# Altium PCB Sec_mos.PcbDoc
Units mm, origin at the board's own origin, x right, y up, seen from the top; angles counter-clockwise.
Board outline 45.5 x 37.75 mm, 4 copper layers (Top Layer, Layer 1, Layer 2, Bottom Layer), stack 1.047 mm thick; 33 components, 16 nets, 98 pads, 225 vias.
Unrouted connection lines stored in the file: 1.
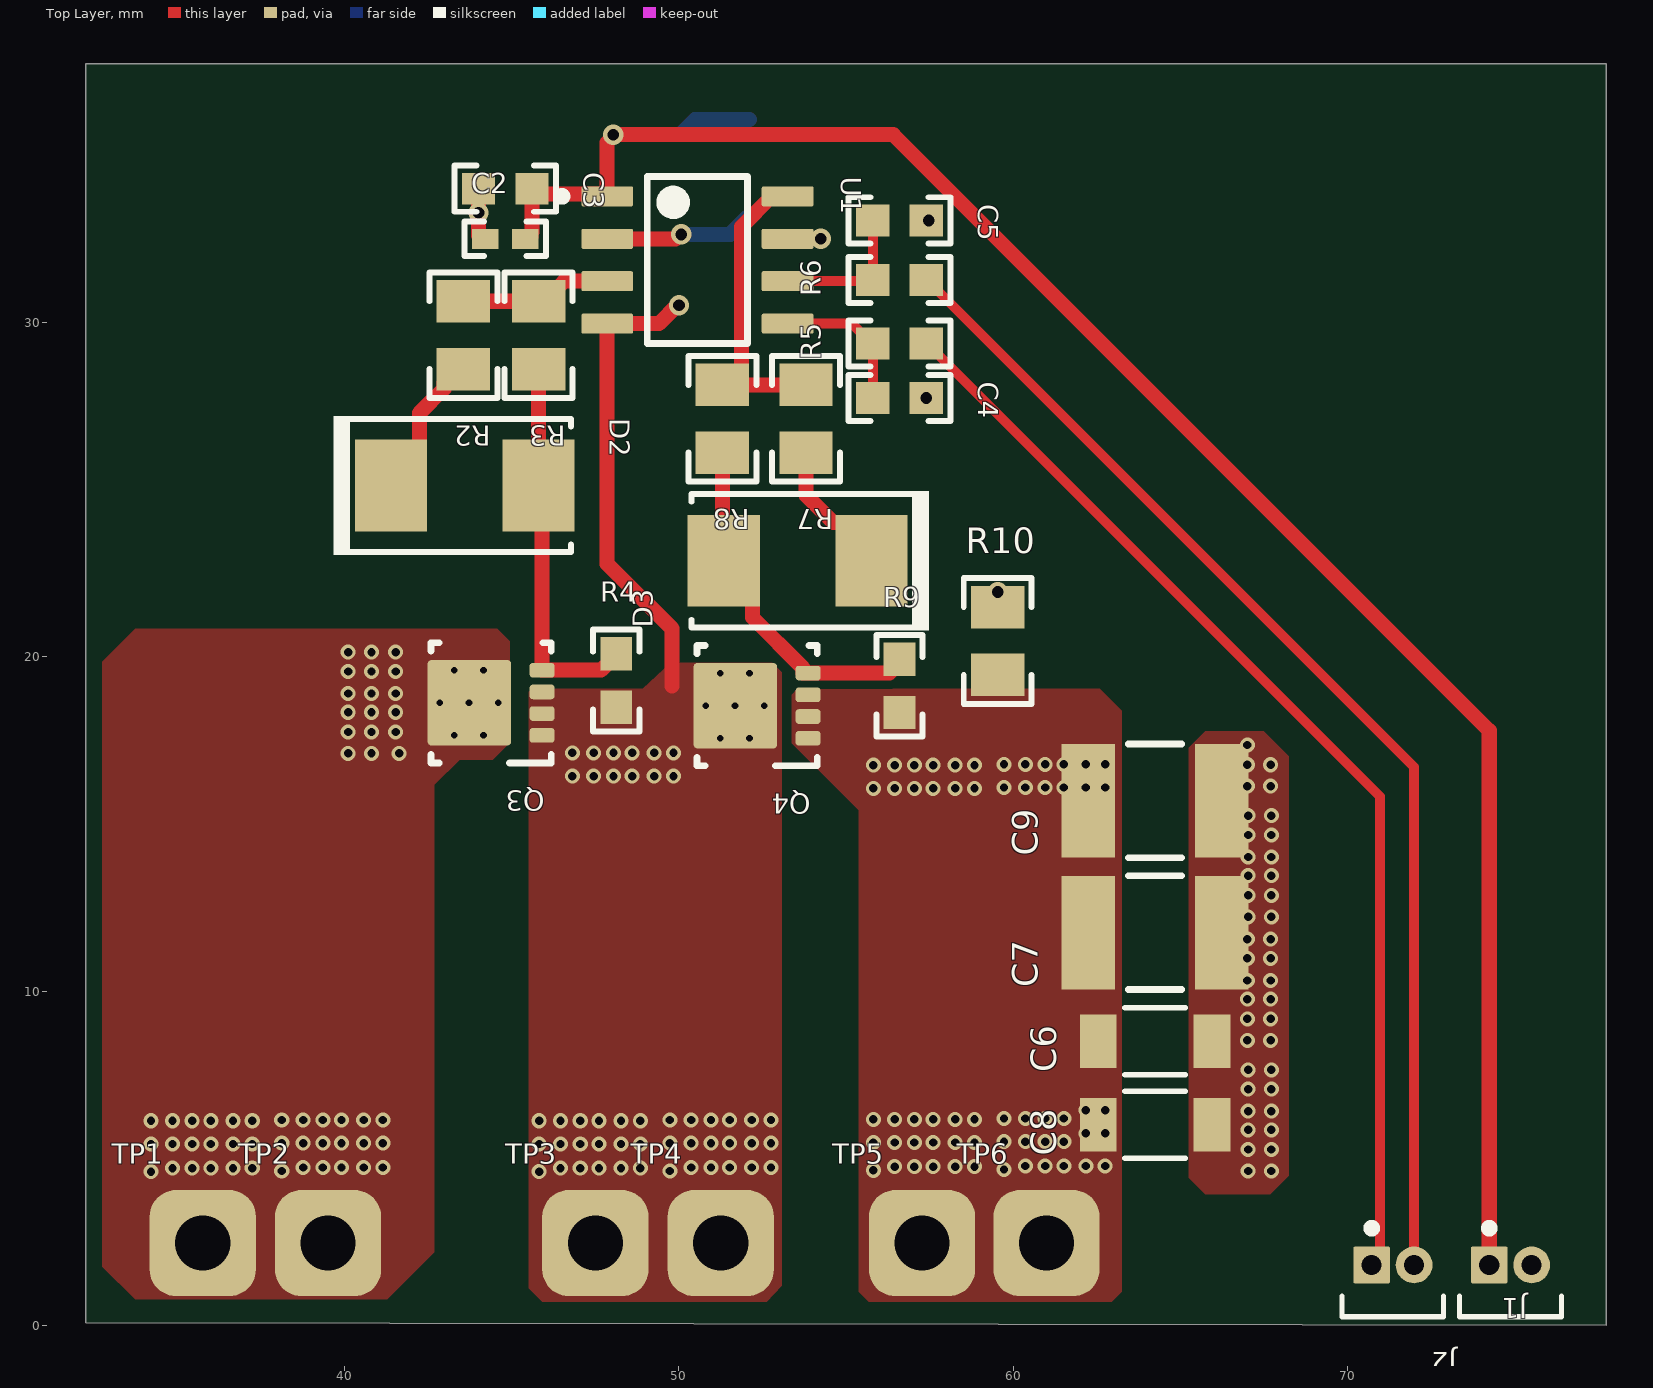
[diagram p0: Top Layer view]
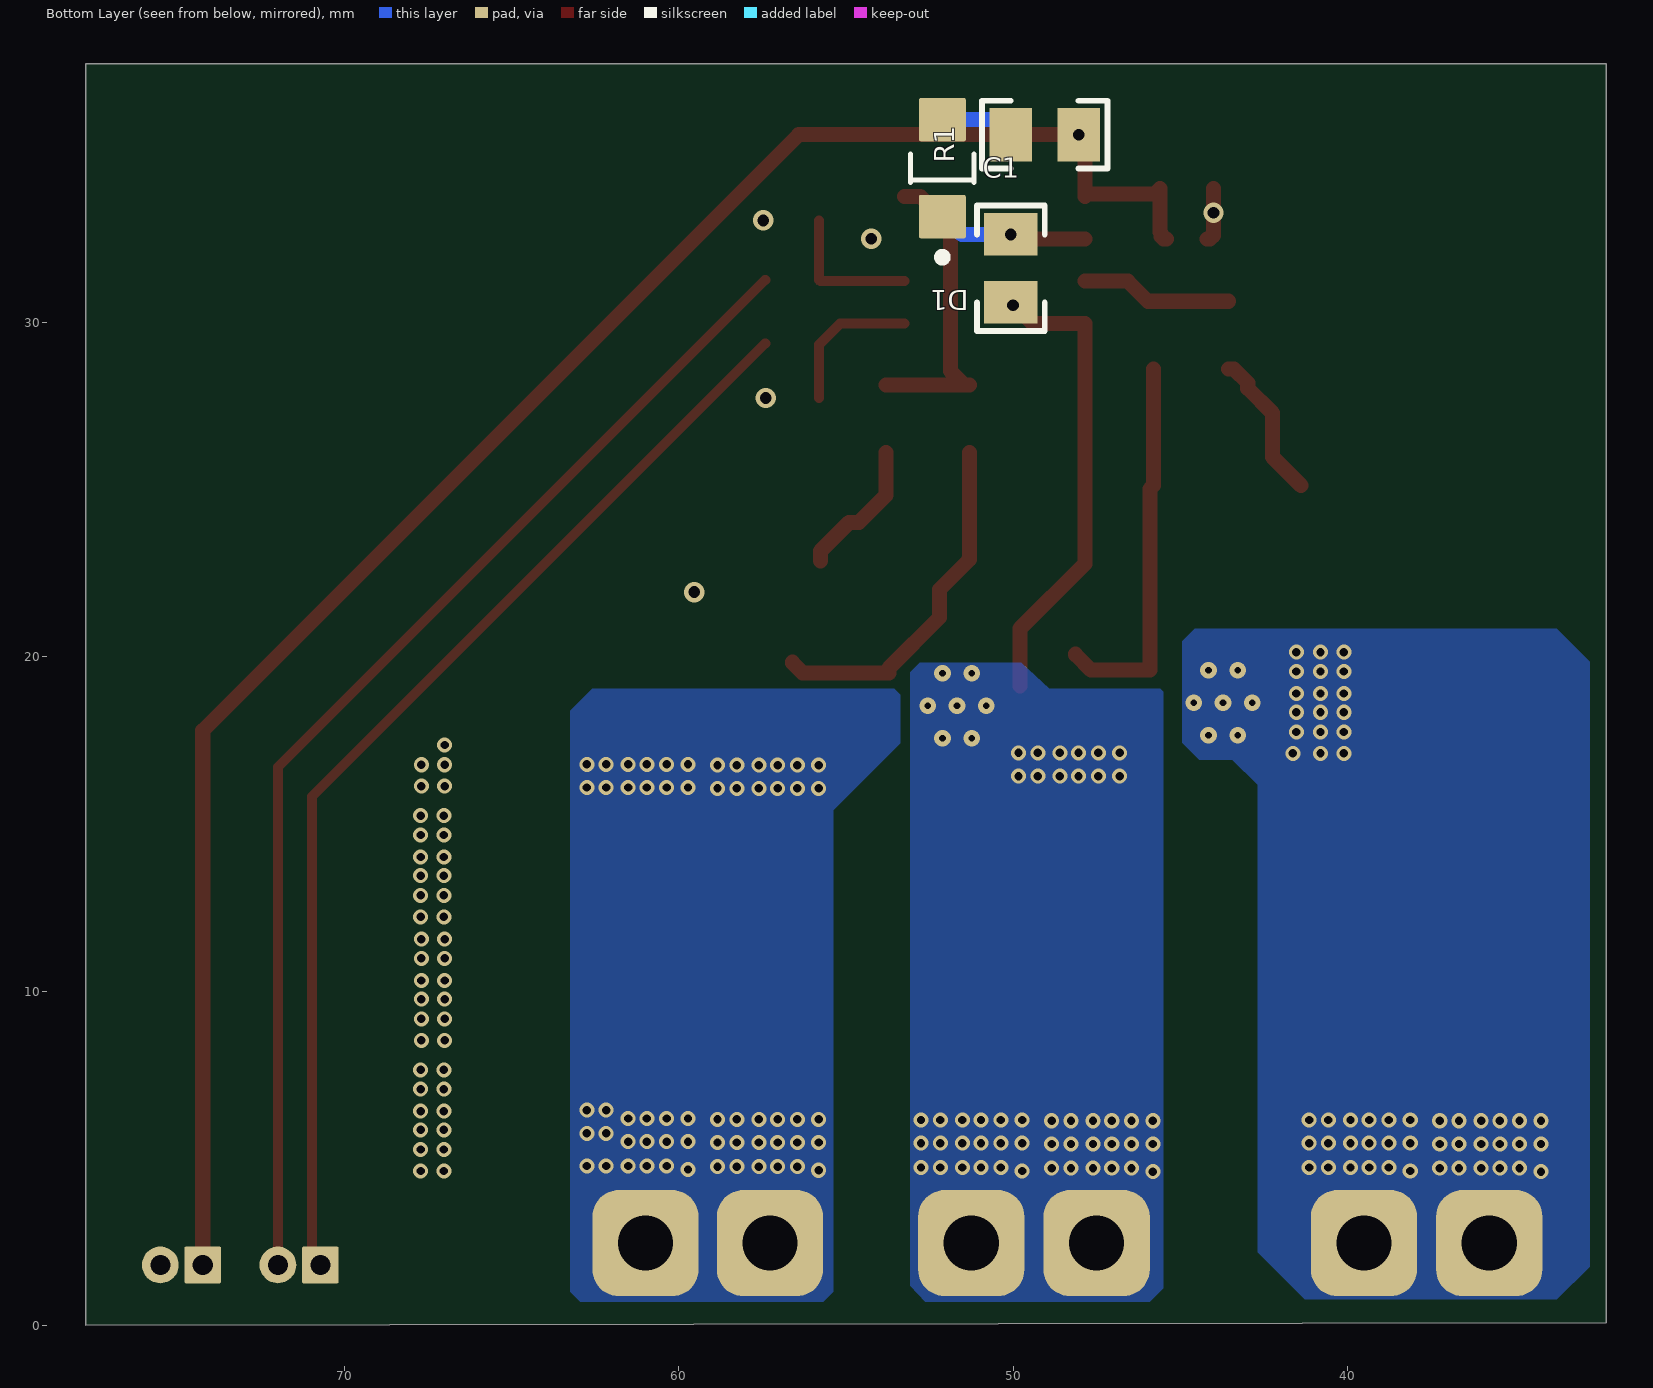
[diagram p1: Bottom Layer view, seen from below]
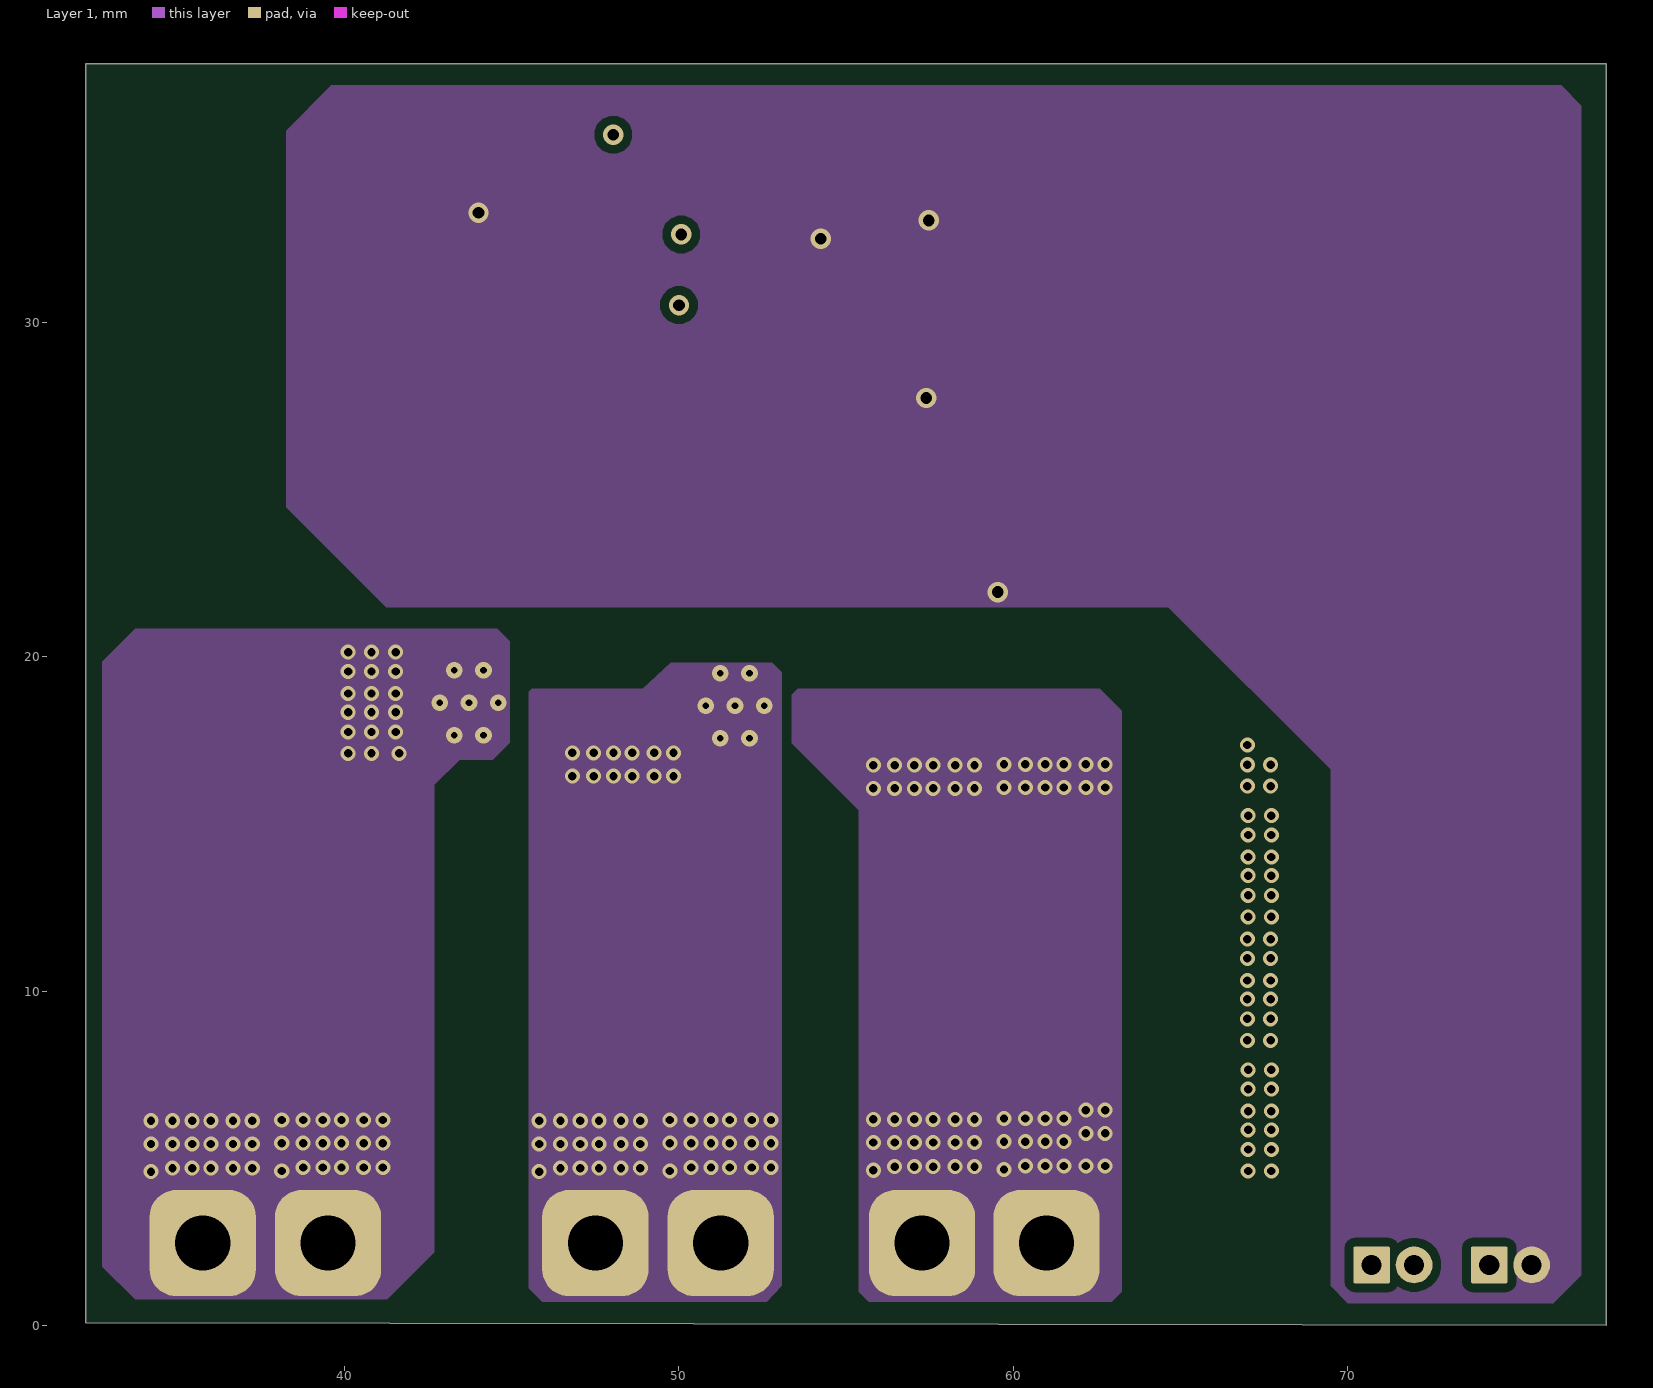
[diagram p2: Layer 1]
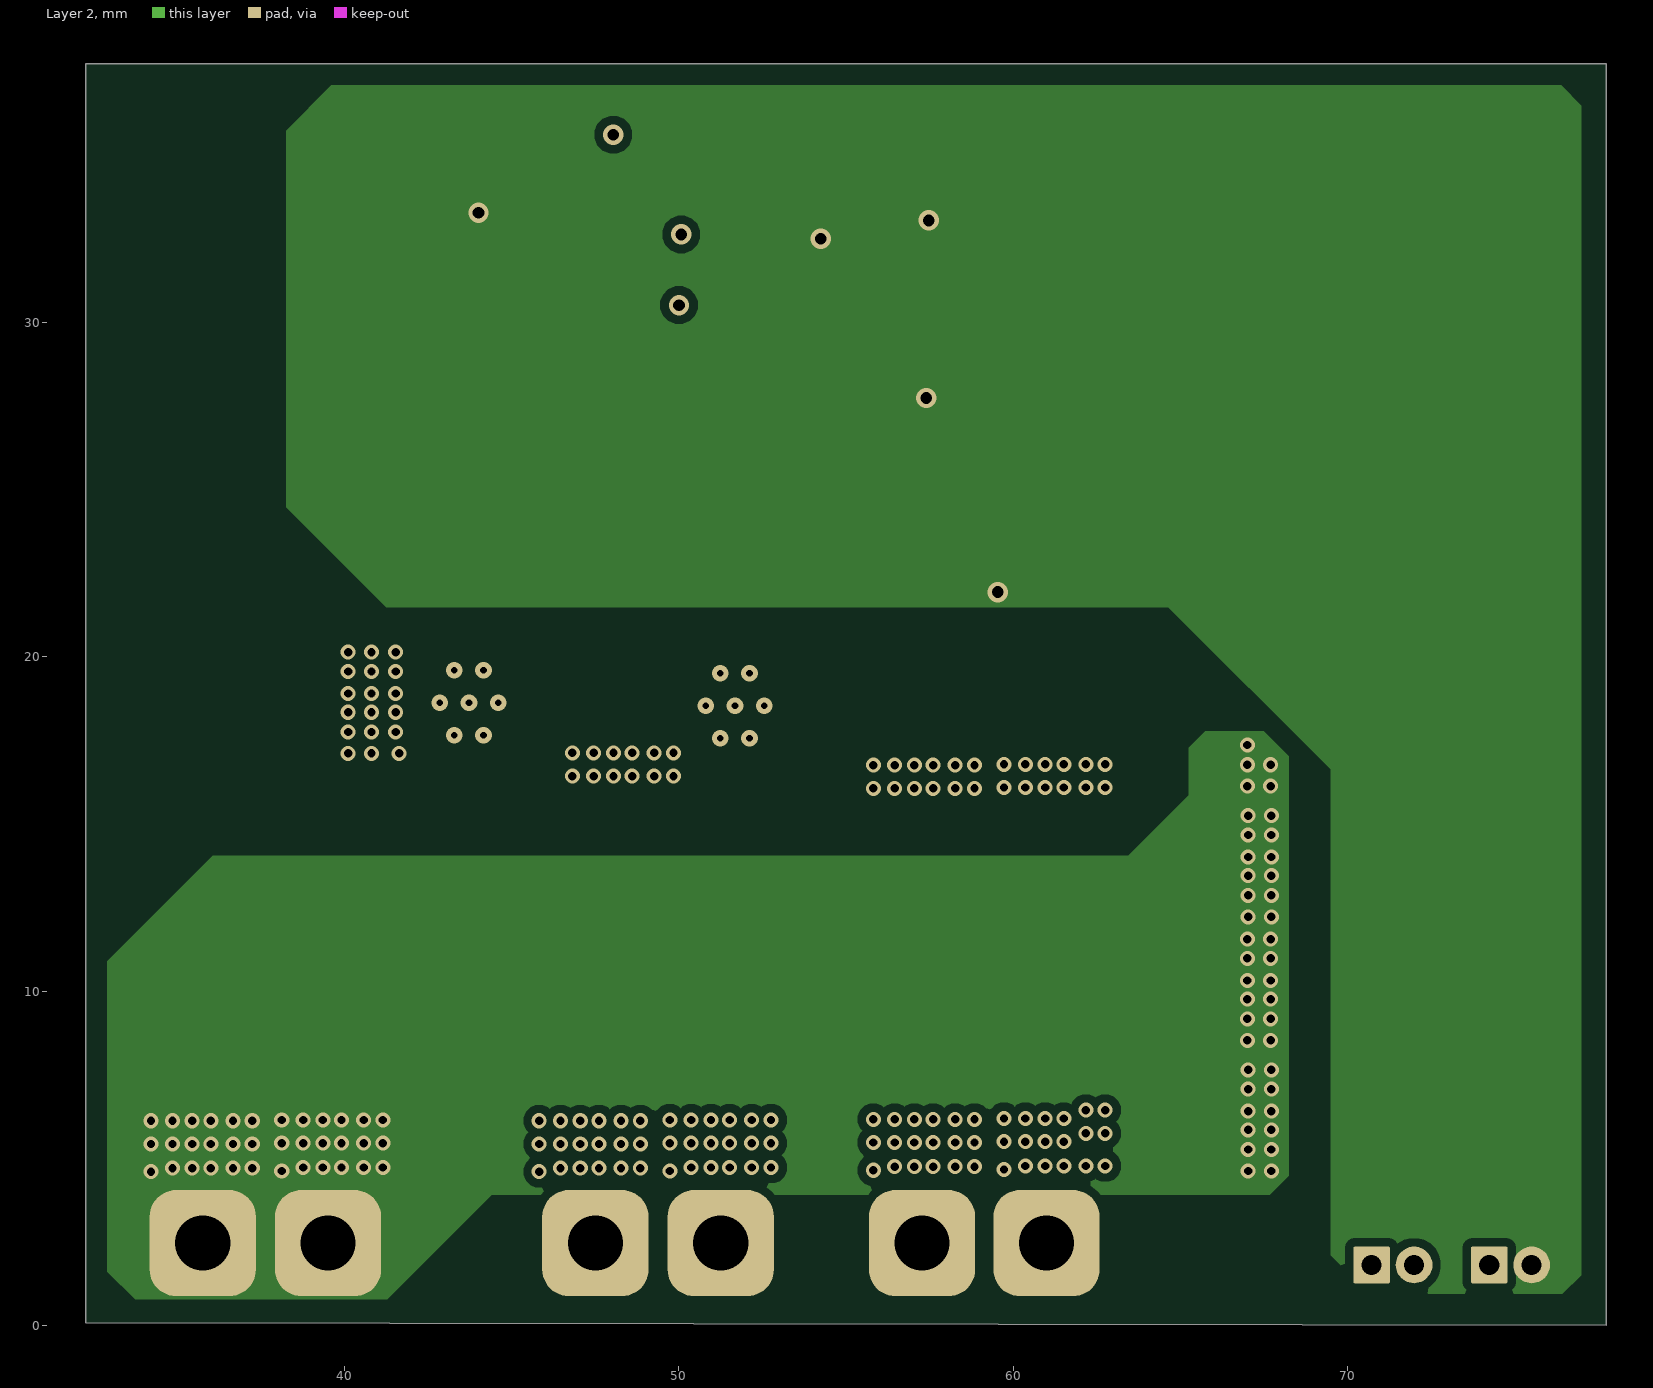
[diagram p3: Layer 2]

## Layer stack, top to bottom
Top Solder: solder mask 0.0102, Solder Resist, Dk 3.5
Top Layer: signal copper 0.07
Dielectric 1: prepreg 0.1168, PP-016, Dk 4.4
Layer 1: signal copper 0.07
Dielectric1: core 0.5334, Core-037, Dk 4.8
Layer 2: signal copper 0.07
Dielectric 2: prepreg 0.1168, PP-016, Dk 4.4
Bottom Layer: signal copper 0.07
Bottom Solder: solder mask 0.0102, Solder Resist, Dk 3.5

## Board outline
32.25,0.07 32.25,37.75 77.75,37.75 77.75,0

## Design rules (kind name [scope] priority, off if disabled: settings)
AcuteAngle [All] p1: minimum=4.50000000000000E+0001 checktracksonly=FALSE
AssemblyTestPointUsage [All] p1: valid=2
BoardOutlineClearance BoardOutlineClearance_MountingHoles [OnCopper and InComponentClass('Mounting Holes')] p1: gap=1 ignorepadtopadclearanceinfootprint=FALSE
BoardOutlineClearance BoardOutlineClearance_Poly [OnCopper and IsPoly] p2: gap=0.635 ignorepadtopadclearanceinfootprint=FALSE
BoardOutlineClearance [OnCopper and Not InComponentClass('Logo') and not InComponentClass('FiducialMark') and not InRegion(1000,500,4000,800) and not InPoly] p3: gap=1.016 ignorepadtopadclearanceinfootprint=FALSE
Clearance Clearance_Keepouts [((IsTrack Or IsArc) And Not InPoly) And IsFree and IsKeepOut vs ((IsTrack Or IsArc) And Not InPoly) And IsFree and IsKeepOut] p1: gap=0 ignorepadtopadclearanceinfootprint=FALSE
Clearance Clearance_Poly [InPolygon] p2: gap=0.254 ignorepadtopadclearanceinfootprint=TRUE
Clearance Clearance_FiducialMark [IsKeepOut and InComponentClass('FiducialMark') vs IsPad and InComponentClass('FiducialMark')] p3: gap=0 ignorepadtopadclearanceinfootprint=FALSE
Clearance [All] p4: gap=0.2 ignorepadtopadclearanceinfootprint=TRUE
ComponentClearance ComponentClearance_MountingHoles_FiducialMarks [InComponentClass('Mounting Holes') vs InComponentClass('FiducialMark')] p1: gap=1.27 collisioncheckmode=3 verticalgap=0.254 showdistances=FALSE
ComponentClearance ComponentClearance_Shunt [InComponentClass('Header') vs InComponentClass('Shunt')] p2: gap=0 collisioncheckmode=3 verticalgap=0 showdistances=FALSE
ComponentClearance ComponentClearance_Logo [InComponentClass('Logo')] p3: gap=0.762 collisioncheckmode=3 verticalgap=0.254 showdistances=FALSE
ComponentClearance ComponentClearance_ScrewToNut [(HasFootprint('NY PMS 440 0025 PH')) vs (HasFootprint('Keystone_1902C'))] p4: gap=0.127 collisioncheckmode=3 verticalgap=0.254 showdistances=FALSE
ComponentClearance ComponentClearance_MountingHoles [InComponentClass('Mounting Holes')] p5: gap=2.54 collisioncheckmode=3 verticalgap=2540 showdistances=FALSE
ComponentClearance ComponentClearance_SmallPassives [HasFootprint('0201*') or HasFootprint('0402*') or HasFootprint('0508') or HasFootprint('0603*') or HasFootprint('0612') or HasFootprint('0805*') or HasFootprint('0815*') or HasFootprint('0830*') or HasFootprint('1206*') or HasFootprint('1210*') or HasFootprint('1808*') or HasFootprint('1812*') or HasFootprint('1825*') or HasFootprint('2010*') or HasFootprint('2220*') or HasFootprint('2225*') or HasFootprint('2512*') or HasFootprint('2728*') or HasFootprint('3518*') vs HasFootprint('0201*') or HasFootprint('0402*') or HasFootprint('0508') or HasFootprint('0603*') or HasFootprint('0612') or HasFootprint('0805*') or HasFootprint('0815*') or HasFootprint('0830*') or HasFootprint('1206*') or HasFootprint('1210*') or HasFootprint('1808*') or HasFootprint('1812*') or HasFootprint('1825*') or HasFootprint('2010*') or HasFootprint('2220*') or HasFootprint('2225*') or HasFootprint('2512*') or HasFootprint('2728*') or HasFootprint('3518*')] p6: gap=0.38 collisioncheckmode=3 verticalgap=0.254 showdistances=FALSE
ComponentClearance ComponentClearance_THtoSMT [IsThruComponent vs IsSMTComponent] p7: gap=0.762 collisioncheckmode=3 verticalgap=0.762 showdistances=FALSE
ComponentClearance ComponentClearance_THtoTH [IsThruComponent vs IsThruComponent] p8: gap=0.508 collisioncheckmode=3 verticalgap=0.762 showdistances=FALSE
ComponentClearance [All] p9: gap=0.508 collisioncheckmode=3 verticalgap=0.254 showdistances=FALSE
DiffPairsRouting [All] p1: maxlimit=2.54 minlimit=0.254 mostfreqgap=0.254 toplayer_minwidth=0.381 toplayer_maxwidth=0.381 toplayer_prefwidth=0.381 midlayer1_minwidth=0.381 midlayer1_maxwidth=0.381 midlayer1_prefwidth=0.381 midlayer2_minwidth=0.381 midlayer2_maxwidth=0.381 midlayer2_prefwidth=0.381 bottomlayer_minwidth=0.381 bottomlayer_maxwidth=0.381 bottomlayer_prefwidth=0.381 maxuncoupledlength=25.4
FabricationTestPointUsage TestPointUsage [All] p1: valid=2 allowmultiple=FALSE
FabricationTestpoint Testpoint [All] p1: side=3 testpointundercomponent=TRUE minsize=1.016 maxsize=2.54 preferedsize=1.524 minholesize=0 maxholesize=1.016 preferedholesize=0.813 testpointgrid=0.025 allowsidetop=TRUE allowsidebottom=TRUE usegrid=TRUE gridtolerance=0
FanoutControl Fanout_LCC [IsLCC] p1: bgadir=Out bgaviamode=Centered fanoutstyle=Auto fanoutdirection=Alternating viagrid=0.025 // Fanout_LCC (Default Rule)
FanoutControl Fanout_BGA [IsBGA] p2: bgadir=Out bgaviamode=Centered fanoutstyle=Auto fanoutdirection=Alternating viagrid=0.025 // Fanout_BGA (Default Rule)
FanoutControl Fanout_Default [All] p4: bgadir=Out bgaviamode=Centered fanoutstyle=Auto fanoutdirection=Alternating viagrid=0.025 // Fanout_Default (Default Rule)
FanoutControl Fanout_Small [(CompPinCount < 5)] p5: bgadir=Out bgaviamode=Centered fanoutstyle=Auto fanoutdirection=OutThenIn viagrid=0.025 // Fanout_Small (Default Rule)
HoleSize [All] p1: absolutevalues=TRUE maxlimit=6.375 minlimit=0.2 maxpercent=80.000 minpercent=20.000
MinimumAnnularRing MinimumAnnularRing_ThermalPadVias [IsVia and InAnyComponent] p1: minimumring=0.15
MinimumAnnularRing [All] p2: minimumring=0.2
MinimumSolderMaskSliver MinimumSolderMaskSliver_Logo [InComponentClass('Logo') vs InComponentClass('Logo')] p1: minsoldermaskwidth=0.018
MinimumSolderMaskSliver [All] p2: minsoldermaskwidth=0.1
PlaneConnect [All] p1: planeconnectstyle=Relief reliefexpansion=0.254 reliefentries=4 reliefconductorwidth=0.254 reliefairgap=0.254
PolygonConnect [All] p1: connectstyle=Direct reliefconductorwidth=0.254 reliefentries=4 polygonreliefangle="90 Angle" airgapwidth=0.254
RoomDefinition Sec_mos [InComponentClass('Sec_mos')] p1: confinementstyle=ConfineIn formatcopy=TRUE lockcomponents=FALSE outline -17.577,-38.964 33.223,-38.964 33.223,-13.564 -17.577,-13.564
RoutingLayers [All] p1: top layer_v5=TRUE mid layer 1_v5=FALSE mid layer 2_v5=FALSE bottom layer_v5=TRUE
RoutingVias ThermalPadVias [IsVia and InAnyComponent] p1: holewidth=0.2 width=0.5 viastyle="Through Hole" minholewidth=0.2 minwidth=0.5 maxholewidth=0.33 maxwidth=0.6
RoutingVias [All] p2: holewidth=0.406 width=0.864 viastyle="Through Hole" minholewidth=0.2 minwidth=0.61 maxholewidth=1.016 maxwidth=1.651
SilkToBoardRegionClearance [Not ((IsComment or IsDesignator) And (Hide <> 'False')) and not InRegion(1000,500,4000,800)] p1:
SilkToSilkClearance SilkToSilkClearance_Pb-FreeLogo [(HasFootprint('Pb-Free_Overlay_Medium') OR HasFootprint('Pb-Free_Overlay_Small')) vs (HasFootprint('Pb-Free_Overlay_Medium') OR HasFootprint('Pb-Free_Overlay_Small'))] p1: silktosilkclearance=0
SilkToSilkClearance [All] p2: silktosilkclearance=0.1
SilkToSolderMaskClearance SilkToComponentPadClearance [(IsPad or IsFill or IsRegion) and InAnycomponent] p1: minsilkscreentomaskgap=0.127 clearancetoexposedcopper=TRUE
SilkToSolderMaskClearance "Silk to Solder Mask Opening" [All] p2: minsilkscreentomaskgap=0.1 clearancetoexposedcopper=FALSE
SolderMaskExpansion [All] p1: expansion=0.05 istentingtop=FALSE
UnRoutedNet [All] p1: checkbadconnections=TRUE
Width [All] p1: maxlimit=2.54 minlimit=0.152 preferedwidth=0.254 checkconnectedcopper=TRUE
13 further rules are at their usual default settings.

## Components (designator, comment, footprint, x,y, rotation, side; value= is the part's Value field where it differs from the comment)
C1 "08055C473JAT2A" 0805_HV 50.069,31.628 r90 bottom value=0.047uF
C2 "0402YC104KAT2A" 0402 44.803,32.513 r0 top value=0.1uF
C3 "GRM188Z71C475KE21D" 0603 44.803,34.013 r0 top value=4.7uF
C4 "06035A101FAT2A" 0603 56.603,27.748 r0 top value=100pF
C5 "06035A101FAT2A" 0603 56.603,33.063 r0 top value=100pF
C6 "C1206C223KDRACTU" 1206_190 64.25,8.5 r180 top value=0.022uF
C7 "C1812W104KDRACTU" 1812_254 64.25,11.75 r180 top value=0.1uF
C8 "C1206C223KDRACTU" 1206_190 64.25,6 r180 top value=0.022uF
C9 "C1812W104KDRACTU" 1812_254 64.25,15.694 r180 top value=0.1uF
D1 "V1FM10-M3/H" FP-V1FM10-M3-H_DO-219AB-MFG 52.115,34.628 r270 bottom
D2 "VS-20BQ030HM3/5BT" SMB 43.593,25.128 r0 top value=30V
D3 "VS-20BQ030HM3/5BT" SMB 53.553,22.878 r180 top value=30V
J1 "M50-3930242" FP-M50-3930242_HDR2-MFG 71.365,0.804 r0 top
J2 "M50-3930242" FP-M50-3930242_HDR2-MFG 74.885,0.804 r0 top
Q3 "CSD19537Q3" DQG0008A 44.38,18.628 r180 top value=100V
Q4 "CSD19537Q3" DQG0008A 52.341,18.54 r180 top value=100V
R1 "RC0805JR-072RL" 0805_HV 49.053,35.628 r0 bottom value=2.0
R2 "MCR10EZPJ000" 0805_HV 43.553,29.628 r270 top value=0
R3 "RC0805JR-071RL" 0805_HV 45.803,29.628 r270 top value=1.0
R4 "RT0603BRD07100KL" 0603 48.128,19.29 r90 top value=100k
R5 "TNPW060310R0BEEA" 0603 56.603,29.378 r180 top value=10.0
R6 "TNPW060310R0BEEA" 0603 56.603,31.278 r180 top value=10.0
R7 "MCR10EZPJ000" 0805_HV 53.803,27.128 r270 top value=0
R8 "RC0805JR-071RL" 0805_HV 51.303,27.128 r270 top value=1.0
R9 "RT0603BRD07100KL" 0603 56.603,19.136 r90 top value=100k
R10 "PMR10EZPJ000" 0805_HV 59.539,20.476 r90 top value=0
TP1 "3621-0-32-15-00-00-08-0" Mill-Max_3621-0-32-xx-00-00-08-0 35.75,0.07 r0 top
TP2 "3621-0-32-15-00-00-08-0" Mill-Max_3621-0-32-xx-00-00-08-0 39.5,0.07 r0 top
TP3 "3621-0-32-15-00-00-08-0" Mill-Max_3621-0-32-xx-00-00-08-0 47.5,0.07 r0 top
TP4 "3621-0-32-15-00-00-08-0" Mill-Max_3621-0-32-xx-00-00-08-0 51.25,0.07 r0 top
TP5 "3621-0-32-15-00-00-08-0" Mill-Max_3621-0-32-xx-00-00-08-0 57.275,0.07 r0 top
TP6 "3621-0-32-15-00-00-08-0" Mill-Max_3621-0-32-xx-00-00-08-0 61,0.07 r0 top
U1 "UCC27288D" D0008A-MFG 50.553,31.878 r0 top

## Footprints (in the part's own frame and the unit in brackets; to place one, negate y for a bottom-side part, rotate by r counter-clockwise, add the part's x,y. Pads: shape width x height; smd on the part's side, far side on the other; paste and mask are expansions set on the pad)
0402 [mm] "0402 from SM-752 data"
  rect 0.8x0.6 smd: 1(-0.6,0) 2(0.6,0)
  silkscreen extent -1.22,-0.52 1.22,0.52, body extent -0.55,-0.3 0.55,0.3, height 0.6
0603 [mm] "0603 from SM-752 data"
  rect 1x0.95 smd: 1(-0.8,0) 2(0.8,0)
  silkscreen extent -1.52,-0.69 1.52,0.69, body extent -0.87,-0.47 0.87,0.47, height 1
0805_HV [mil] "0805 with 30mil clearance between pads"
  rect 50x63 smd: 1(-40,0) 2(40,0)
  silkscreen extent -74,-40 74,40, body extent -43,-29 43,29, height 57
1206_190 [mm] "1206_190"
  rect 1.1x1.6 smd: 1(-1.7,0) 2(1.7,0)
  silkscreen extent -0.9,-1 0.9,1, body extent -1.75,-0.95 1.75,0.95, height 1.9
1812_254 [mm] "SMD, 2-Leads, Body 4.8x3.4mm"
  rect 1.6x3.4 smd: 1(-2,0) 2(2,0)
  silkscreen extent -0.8,-1.7 0.8,1.7, body extent -2.4,-1.7 2.4,1.7, height 2.54
D0008A-MFG [mm]
  rrect17% 1.55x0.6 smd paste+0 mask+0: 1(-2.7,1.905) 2(-2.7,0.635) 3(-2.7,-0.635) 4(-2.7,-1.905) 5(2.7,-1.905) 6(2.7,-0.635) 7(2.7,0.635) 8(2.7,1.905)
  silkscreen extent -4.17,-2.5 1.5,2.5, body extent -3.57,-2.75 3.57,2.75, height 0.25
DQG0008A [mm] "SMD, 8-Leads, Body 3.3x3.3mm, Pitch 0.65mm"
  rrect45% 0.75x0.44 smd paste-0.05 mask-0.05: 1(-1.525,0.975) 2(-1.525,0.325) 3(-1.525,-0.325) 4(-1.525,-0.975) 5(1.525,-0.975) 6(1.525,-0.325) 7(1.525,0.325) 8(1.525,0.975)
  rrect15% 0.676x1.125 on Top Paste: 9(-0.212,0.662) 9(-0.212,-0.663) 9(0.664,0.662) 9(0.664,-0.663)
  rrect6% 1.775x2.45 on Top Solder: 9(0.327,0)
  rrect8% 2.5x2.55 smd paste-1.5 mask-1.5: 9(0.65,0)
  rrect29% 0.5x0.34 on Top Solder: 9(1.175,0.975) 9(1.175,-0.325) 9(1.175,0.325) 9(1.175,-0.975)
  silkscreen extent -1.8,-1.8 1.8,1.8, body extent -1.65,-1.65 1.65,1.65, height 1.1
FP-M50-3930242_HDR2-MFG [mm]
  rrect9% 1.1x1.1 hole 0.6 paste-1000 mask+0: 1(-0.635,1)
  round 1.1 hole 0.6 paste-1000 mask+0: 2(0.635,1)
  silkscreen extent -1.52,-0.55 1.52,2.22, body extent -1.62,-4.85 1.62,1.65, height 0.25
FP-V1FM10-M3-H_DO-219AB-MFG [mm]
  rrect8% 1.3x1.4 smd paste+0 mask+0: 1(1.45,0) 2(-1.45,0)
  silkscreen extent -0.43,-0.95 2.79,0.95, body extent -1.85,-0.9 1.85,0.9, height 1.08
Mill-Max_3621-0-32-xx-00-00-08-0 [mm] "PCB Pin, 0.04\" DIA, R/A, Edge-Mount"
  rrect50% 3.18x3.18 hole 1.65: 1(0,2.388)
  body extent -1.59,-5.06 1.59,3.98, height 1.57
SMB [mm] "Molded Diode, 2-Leads, Body 5.4x3.6mm, IPC Medium Density, based on OnSemi component dimensions"
  rect 2.159x2.743 smd: 1(-2.21,0) 2(2.21,0)
  silkscreen extent -3.94,-2.08 3.17,2.08, body extent -2.7,-1.8 2.7,1.8, height 2.32

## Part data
C1: library part CMP-0007658-2, "CAP, CERM, 0.047 uF, 50 V, +/- 5%, X7R, 0805", Cap_Case=0805, Manufacturer=AVX, Supplier Part Number 1=478-3771-1-ND, TempCo=X7R, Tolerance_%=5%, Value1="0.035 ohm", Value2=50V, ValueDisplayed=0.047uF
C2: library part CMP-0006201-2, "CAP, CERM, 0.1 uF, 16 V, +/- 10%, X7R, 0402", Cap_Case=0402, Manufacturer=AVX, Supplier Part Number 1=478-7888-1-ND, TempCo=X7R, Tolerance_%=10%, Value1=Unknown, Value2=16V, ValueDisplayed=0.1uF
C3: library part CMP-0064936-4, "CAP, CERM, 4.7 uF, 16 V,+/- 10%, X7R, 0603", Cap_Case=0603, Manufacturer=MuRata, TempCo=X7R, Tolerance_%=10%, Value1=Unknown, Value2=16V, ValueDisplayed=4.7uF
C4 C5: library part CMP-0006762-4, "CAP, CERM, 100 pF, 50 V, +/- 1%, C0G/NP0, 0603", Cap_Case=0603, Manufacturer=AVX, Supplier Part Number 1=478-6202-1-ND, TempCo=C0G/NP0, Tolerance_%=1%, Value1=Unknown, Value2=50V, ValueDisplayed=100pF
C6 C8: library part CMP-0084048-1, "CAP, CERM, 0.022 µF, 1000 V,+/- 10%, X7R, AEC-Q200 Grade 1, 1206", Cap_Case=1206, Manufacturer=Kemet, TempCo=X7R, Tolerance_%=10%, Value2=1000V, ValueDisplayed=0.022µF
C7 C9: library part CMP-0009326-2, "CAP, CERM, 0.1 uF, 1000 V, +/- 10%, X7R, 1812", Cap_Case=1812, Manufacturer=Kemet, Supplier Part Number 1=399-6523-1-ND, TempCo=X7R, Tolerance_%=10%, Value1=Unknown, Value2=1000V, ValueDisplayed=0.1uF
D1: library part CMP-0093639-2, "Diode Schottky 1A Surface Mount DO-219AB (SMF)", Digikey Part Number=112-V1FM10-M3/HCT-ND, Forward Current=1A, Manufacturer=Vishay, Max Surge Forward Current=30A, Mouser Part Number=78-V1FM10-M3/H, Operating Temperature Range="-40°C to +175°C", Peak Reverse Current=0.2uA, ValueDisplayed=95pF
D2 D3: library part CMP-0028909-2, "Diode, Schottky, 30 V, 2 A, AEC-Q101, SMB", Manufacturer=Vishay-Semiconductor, Value1=2A, Value2=0.47V
J1 J2: library part CMP-0097272-1, "Conn Unshrouded HDR 2 POS 1.27mm Solder RA Through Hole Box", Current_A=1A, Digikey Part Number=952-3614-ND, Manufacturer=Harwin, Mouser Part Number=855-M50-3930242, Operating Temperature Range="-40°C to +105°C"
Q3 Q4: library part CMP-0000967-2, "MOSFET, N-CH, 100 V, 50 A, DQG0008A (VSON-CLIP-8)", Alternate Manufacturer=None, Manufacturer="Texas Instruments", Supplier Part Number 1=CSD19537Q3-ND, Value2="16 nC"
R1: library part CMP-0020815-2, "RES, 2.0, 5%, 0.125 W, 0805", Manufacturer="Yageo America", Power_W=125mW, Supplier Part Number 1=311-2.0ARCT-ND, TempCo="200 ppm/C", Tolerance_%=5%, Value2=0.125W, Value_Code=2R00, ValueDisplayed=2.0
R2 R7: library part CMP-0020802-2, "RES, 0, 5%, 0.125 W, 0805", Manufacturer=Rohm, Power_W=125mW, Supplier Part Number 1=RHM0.0ARCT-ND, TempCo="400 ppm/C", Tolerance_%=5%, Value2=0.125W, Value_Code=0000, ValueDisplayed=0
R3 R8: library part CMP-0020811-2, "RES, 1.0, 5%, 0.125 W, 0805", Manufacturer="Yageo America", Power_W=125mW, Supplier Part Number 1=311-1.0ARCT-ND, TempCo="200 ppm/C", Tolerance_%=5%, Value2=0.125W, Value_Code=1R00, ValueDisplayed=1.0
R4 R9: library part CMP-0023630-3, "RES, 100 k, 0.1%, 0.1 W, 0603", Manufacturer="Yageo America", Power_W=100mW, Supplier Part Number 1=603-RT0603BRD07100KL, TempCo="25 ppm/C", Tolerance_%=0.1%, Value2=0.1W, Value_Code=100k
R5 R6: library part CMP-0025687-2, "RES, 10.0, 0.1%, 0.1 W, 0603", Manufacturer=Vishay-Dale, Power_W=100mW, Supplier Part Number 1=TNP10.0AACT-ND, TempCo="25 ppm/C", Tolerance_%=0.1%, Value2=0.1W, Value_Code=10R0, ValueDisplayed=10.0
R10: library part CMP-0081857-1, "RES, 0, 0%,  W, AEC-Q200 Grade 0, 0805", Manufacturer=Rohm, Supplier Part Number 1=755-PMR10EZPJ000, Tolerance_%=0%, Value2=W, Value_Code=0
TP1 TP2 TP3 TP4 TP5 TP6: library part CMP-0082316-1, "PCB Pin, 0.04\" DIA, Edge-Mount", Manufacturer=Mill-Max, Supplier Part Number 1=575-3621032150000
U1: library part CMP-0088395-1, "120-V Boot, 3-A Peak, High-Frequency High-Side/Low-Side Driver", Manufacturer="Texas Instruments", Max Supply Voltage=16V, Min Supply Voltage=8V, Nominal Supply Current=2.2uA, Operating Temperature Range="-40°C to +140°C"

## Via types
v1: diameter 0.45, hole 0.25, Top Layer to Bottom Layer, tented both sides, 203 vias
v2: diameter 0.5, hole 0.2, Top Layer to Bottom Layer, 12 vias
v3: diameter 0.61, hole 0.35, Top Layer to Bottom Layer, tented both sides, 8 vias
v4: diameter 0.5, hole 0.2, Top Layer to Bottom Layer, tented both sides, 2 vias

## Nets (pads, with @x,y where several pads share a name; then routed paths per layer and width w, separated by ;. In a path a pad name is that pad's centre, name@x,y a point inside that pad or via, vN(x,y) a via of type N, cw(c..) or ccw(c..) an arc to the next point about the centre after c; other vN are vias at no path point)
+12V: C2.2 C3.2 J2.1 R1.1 U1.1 | length 55
  Top Layer w0.45: C2.2 45.503,32.513 45.578,32.588 45.578,32.688 45.603,32.713 C3.2 45.758,33.858 47.778,33.858 U1.1 v3@47.853,35.401 ; v3(48.037,35.628) 56.414,35.628 74.25,17.792 J2.1@74.25,2.045
GND_sec: C2.1 C3.1 C4.2 C5.2 C6.2 C7.2 C8.2 C9.2 J2.2 Q4.1 Q4.2 Q4.3 R9.1 R10.1 R10.2 TP5.1 TP6.1 U1.7 | length 1.6
  Top Layer w0.45: C3.1 44.003,32.613 44.103,32.513 C2.1
  other v1: 55.817,4.639 59.728,4.662 56.457,4.744 57.048,4.744 57.607,4.744 58.267,4.744 58.845,4.744 60.368,4.767 60.958,4.767 61.517,4.767 62.178,4.767 62.755,4.767 55.817,5.469 56.457,5.469 57.048,5.469 57.607,5.469 58.267,5.469 58.845,5.469 59.728,5.492 60.368,5.492 60.958,5.492 61.517,5.492 62.178,5.742 62.755,5.742 55.817,6.164 56.457,6.164 57.048,6.164 57.607,6.164 58.267,6.164 58.845,6.164 59.728,6.187 60.368,6.187 60.958,6.187 61.517,6.187 62.178,6.437 62.755,6.437 55.817,16.068 56.457,16.068 57.048,16.068 57.607,16.068 58.267,16.068 58.845,16.068 59.728,16.091 60.368,16.091 60.958,16.091 61.517,16.091 62.178,16.091 62.755,16.091 55.817,16.763 56.457,16.763 57.048,16.763 57.607,16.763 58.267,16.763 58.845,16.763 59.728,16.786 60.368,16.786 60.958,16.786 61.517,16.786 62.178,16.786 62.755,16.786
  other v3: 59.539,21.94 57.403,27.748 54.249,32.513 57.478,33.063 44.003,33.288
NetC1_1: C1.1 Q3.1 Q3.2 Q3.3 Q4.5 Q4.6 Q4.7 Q4.8 Q4.9@51.691,18.54 R4.1 TP3.1 TP4.1 U1.4 | length 14
  Top Layer w0.45: 49.789,19.136 49.789,20.847 47.853,22.784 U1.4 49.405,29.973 49.96,30.528 v3(50.003,30.528)
  other v1: 45.817,4.594 49.728,4.617 46.457,4.699 47.048,4.699 47.607,4.699 48.267,4.699 48.845,4.699 50.368,4.722 50.958,4.722 51.517,4.722 52.178,4.722 52.755,4.722 45.817,5.424 46.457,5.424 47.048,5.424 47.607,5.424 48.267,5.424 48.845,5.424 49.728,5.447 50.368,5.447 50.958,5.447 51.517,5.447 52.178,5.447 52.755,5.447 45.817,6.119 46.457,6.119 47.048,6.119 47.607,6.119 48.267,6.119 48.845,6.119 49.728,6.142 50.368,6.142 50.958,6.142 51.517,6.142 52.178,6.142 52.755,6.142 46.81,16.432 47.45,16.432 48.041,16.432 48.6,16.432 49.26,16.432 49.838,16.432 46.81,17.127 47.45,17.127 48.041,17.127 48.6,17.127 49.26,17.127 49.838,17.127
  other v2: 51.239,17.565 52.115,17.565 51.677,18.54 52.553,18.54 51.239,19.515 52.115,19.515
  other v4: 50.801,18.54
NetC1_2: C1.2 D1.1 U1.2 | length 4.5
  Top Layer w0.45: U1.2 49.895,32.513 50.026,32.644 v3(50.069,32.644)
  Bottom Layer w0.45: v3(50.069,32.644) 51.531,32.644 52.065,33.178 D1.1
NetC4_1: C4.1 R5.2 U1.5 | length 4.4
  Top Layer w0.3: U1.5 55.183,29.973 55.803,29.353 C4.1
NetC5_1: C5.1 R6.2 U1.6 | length 4.3
  Top Layer w0.3: U1.6 55.767,31.243 R6.2 C5.1
NetC6_1: C6.1 C7.1 C8.1 C9.1 Q3.5 Q3.6 Q3.7 Q3.8 Q3.9@43.73,18.628 TP1.1 TP2.1
  other v1: 34.204,4.594 38.114,4.617 67.035,4.617 67.73,4.617 34.844,4.699 35.434,4.699 35.993,4.699 36.654,4.699 37.231,4.699 38.754,4.722 39.345,4.722 39.904,4.722 40.564,4.722 41.142,4.722 67.035,5.257 67.73,5.257 34.204,5.424 34.844,5.424 35.434,5.424 35.993,5.424 36.654,5.424 37.231,5.424 38.114,5.447 38.754,5.447 39.345,5.447 39.904,5.447 40.564,5.447 41.142,5.447 67.035,5.848 67.73,5.848 34.204,6.119 34.844,6.119 35.434,6.119 35.993,6.119 36.654,6.119 37.231,6.119 38.114,6.142 38.754,6.142 39.345,6.142 39.904,6.142 40.564,6.142 41.142,6.142 67.035,6.407 67.73,6.407 67.035,7.067 67.73,7.067 67.035,7.645 67.73,7.645 67.012,8.528 67.707,8.528 67.012,9.168 67.707,9.168 67.012,9.758 67.707,9.758 67.012,10.317 67.707,10.317 67.012,10.978 67.707,10.978 67.012,11.555 67.707,11.555 67.035,12.223 67.73,12.223 67.035,12.863 67.73,12.863 67.035,13.453 67.73,13.453 67.035,14.012 67.73,14.012 67.035,14.673 67.73,14.673 67.035,15.25 67.73,15.25 67.012,16.133 67.707,16.133 67.012,16.773 67.707,16.773 40.104,17.114 40.799,17.114 41.629,17.114 67.012,17.364 40.104,17.754 40.799,17.754 41.524,17.754 40.104,18.345 40.799,18.345 41.524,18.345 40.104,18.904 40.799,18.904 41.524,18.904 40.104,19.564 40.799,19.564 41.524,19.564 40.104,20.142 40.799,20.142 41.524,20.142
  other v2: 43.278,17.653 44.154,17.653 43.716,18.628 44.592,18.628 43.278,19.603 44.154,19.603
  other v4: 42.84,18.628
NetD1_2: D1.2 R1.2 | length 2.3
  Bottom Layer w0.45: R1.2 50.069,35.668 50.479,36.078 D1.2
NetD2_1: D2.1 R2.2 | length 4.5
  Top Layer w0.45: D2.1 42.237,25.982 42.237,27.296 42.978,28.037 42.978,28.202 43.388,28.612 R2.2
NetD2_2: D2.2 Q3.4 R3.2 R4.2 | length 11.5
  Top Layer w0.45: R3.2 D2.2 45.905,25.025 Q3.4 47.665,19.603 48.128,20.065 R4.2
NetD3_1: D3.1 R7.2 | length 4.2
  Top Layer w0.45: R7.2 53.803,24.838 54.616,24.024 54.908,24.024 55.763,23.17 D3.1
NetD3_2: D3.2 Q4.4 R8.2 R9.2 | length 10.6
  Top Layer w0.45: R8.2 51.303,22.918 D3.2 52.197,22.023 52.197,21.184 53.716,19.665 53.716,19.52 53.721,19.515 Q4.4 56.295,19.515 56.603,19.823 R9.2@56.603,19.848
NetJ1_1: J1.1 R5.1 | length 33
  Top Layer w0.3: R5.1 57.428,29.378 70.98,15.826 J1.1@70.98,2
NetJ1_2: J1.2 R6.1 | length 35.5
  Top Layer w0.3: R6.1 57.428,31.278 72,16.706 J1.2
NetR2_1: R2.1 R3.1 U1.3 | length 4.5
  Top Layer w0.45: R2.1 R3.1 45.968,30.644 46.567,31.243 U1.3
NetR7_1: R7.1 R8.1 U1.8 | length 9.2
  Top Layer w0.45: R8.1 R8.1@51.468,28.144 ; U1.8 52.778,33.783 51.878,32.883 51.878,28.554 R8.1@51.468,28.144 ; R7.1 R8.1@51.468,28.144
pads on no net: Q3.9@43.205,17.653 Q3.9@43.205,18.303 Q3.9@43.205,18.953 Q3.9@43.205,19.603 Q3.9@43.716,17.965 Q3.9@43.716,19.29 Q3.9@44.053,18.628 Q3.9@44.592,17.965 Q3.9@44.592,19.29 Q4.9@51.166,17.565 Q4.9@51.166,18.215 Q4.9@51.166,18.865 Q4.9@51.166,19.515 Q4.9@51.677,17.878 Q4.9@51.677,19.203 Q4.9@52.013,18.54 Q4.9@52.553,17.878 Q4.9@52.553,19.203

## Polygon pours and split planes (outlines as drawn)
NetC6_1 on Top Layer "TOP_LAYER_NETC6_1_P014" (solid, remove dead copper, pour order 14): 65.75,17.775 65.25,17.275 65.25,4.414 65.75,3.914 67.689,3.914 68.25,4.475 68.25,17.025 67.5,17.775
NetC6_1 on Top Layer "TOP_LAYER_NETC6_1_P000" (solid, remove dead copper, pour order 0): 33.73,20.84 32.75,19.86 32.75,1.751 33.73,0.77 41.27,0.77 42.68,2.18 42.68,16.168 43.44,16.928 44.43,16.928 44.93,17.428 44.93,20.476 44.566,20.84
GND_sec on Top Layer "TOP_LAYER_GND_SEC_P008" (solid, remove dead copper, pour order 8): 53.553,19.048 53.371,18.867 53.371,17.417 55.382,15.406 55.382,1.005 55.688,0.7 62.95,0.7 63.25,1 63.25,18.386 62.587,19.048
NetC1_1 on Top Layer "TOP_LAYER_NETC1_1_P004" (solid, remove dead copper, pour order 4): 45.598,19.048 45.503,18.953 45.503,1.11 45.912,0.7 52.628,0.7 53.078,1.176 53.078,19.54 52.795,19.823 49.756,19.823 48.921,19.048
GND_sec on Layer 1 "LAYER_1_GND_SEC_P012" (solid, remove dead copper, pour order 12): 39.75,37.25 38.25,35.75 38.25,24.475 41.235,21.49 64.646,21.49 69.5,16.636 69.5,1.176 70.128,0.549 76.049,0.549 77,1.5 77,36.5 76.25,37.25
GND_sec on Layer 1 "LAYER_1_GND_SEC_P009" (solid, remove dead copper, pour order 9): 53.553,19.048 53.371,18.867 53.371,17.417 55.382,15.406 55.382,1.005 55.688,0.7 62.95,0.7 63.25,1 63.25,18.386 62.587,19.048
NetC1_1 on Layer 1 "LAYER_1_NETC1_1_P007" (solid, remove dead copper, pour order 7): 45.598,19.048 45.503,18.953 45.503,1.11 45.912,0.7 52.628,0.7 53.078,1.176 53.078,19.54 52.795,19.823 49.756,19.823 48.921,19.048
NetC6_1 on Layer 1 "LAYER_1_NETC6_1_P003" (solid, remove dead copper, pour order 3): 33.73,20.84 32.75,19.86 32.75,1.751 33.73,0.77 41.27,0.77 42.68,2.18 42.68,16.168 43.44,16.928 44.43,16.928 44.93,17.428 44.93,20.476 44.566,20.84
NetC6_1 on Layer 2 "LAYER_2_NETC6_1_P016" (solid, remove dead copper, pour order 16): 33.73,0.77 32.75,1.751 32.75,10.75 36.056,14.056 63.451,14.056 65.25,15.855 65.25,17.275 65.75,17.775 67.5,17.775 68.25,17.025 68.25,4.475 67.681,3.906 44.406,3.906 41.27,0.77
GND_sec on Layer 2 "LAYER_2_GND_SEC_P013" (solid, remove dead copper, pour order 13): 39.75,37.25 38.25,35.75 38.25,24.475 41.235,21.49 64.646,21.49 69.5,16.636 69.5,2.095 70.657,0.938 76.438,0.938 77,1.5 77,36.5 76.25,37.25
GND_sec on Bottom Layer "BOTTOM_LAYER_GND_SEC_P011" (solid, remove dead copper, pour order 11): 53.553,19.048 53.371,18.867 53.371,17.417 55.382,15.406 55.382,1.005 55.688,0.7 62.95,0.7 63.25,1 63.25,18.386 62.587,19.048
NetC1_1 on Bottom Layer "BOTTOM_LAYER_NETC1_1_P005" (solid, remove dead copper, pour order 5): 45.598,19.048 45.503,18.953 45.503,1.11 45.912,0.7 52.628,0.7 53.078,1.176 53.078,19.54 52.795,19.823 49.756,19.823 48.921,19.048
NetC6_1 on Bottom Layer "BOTTOM_LAYER_NETC6_1_P001" (solid, remove dead copper, pour order 1): 33.73,20.84 32.75,19.86 32.75,1.751 33.73,0.77 41.27,0.77 42.68,2.18 42.68,16.168 43.44,16.928 44.43,16.928 44.93,17.428 44.93,20.476 44.566,20.84

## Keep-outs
Keep-Out Layer:
  text ".Layer_Name" at 14.656,-21.806 h0.6

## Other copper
Top Layer:
  text ".Layer_Name" at 14.656,-21.806 h0.6
Bottom Layer:
  text ".Layer_Name" at 14.656,-21.806 h0.6

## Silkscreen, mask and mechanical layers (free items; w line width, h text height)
Top Overlay:
  text ".Layer_Name" at 14.656,-21.806 h0.6
Bottom Overlay:
  text ".Layer_Name" at 14.656,-21.806 h0.6
Top Paste:
  text ".Layer_Name" at 14.656,-21.806 h0.6
Bottom Paste:
  text ".Layer_Name" at 14.656,-21.806 h0.6
Top Solder:
  text ".Layer_Name" at 14.656,-21.806 h0.6
  text ".Layer_Name" at 14.656,-21.806 h0.6
Bottom Solder:
  rectangle: 42.437,17.338 45.148,19.983
  rectangle: 50.368,17.178 53.078,19.823
  text ".Layer_Name" at 14.656,-21.806 h0.6
Drill Guide:
  text ".Layer_Name" at 14.656,-21.806 h0.6
M1 Board Outline:
  the board outline again, w0.254
  text ".Layer_Name" at 14.656,-21.806 h0.6
M2 Board Dimensions:
  rectangle: 0,-6.985 3.175,-3.81
  rectangle: 3.175,-10.16 12.7,-6.985
  lines w0.178: 0,-6.985 25.4,-6.985 ; 3.175,-10.16 3.175,-3.81 ; 6.35,-10.16 6.35,-3.81 ; 12.7,-10.16 12.7,-3.81 ; 19.05,-10.16 19.05,-3.81 ; 0,-10.16 25.4,-10.16 25.4,-3.81 0,-3.81 0,-10.16
  text ".Layer_Name" at 14.656,-21.806 h0.6
M3 3D STEP Top:
  text ".Layer_Name" at 14.656,-21.806 h0.6
M4 3D STEP Bottom:
  text ".Layer_Name" at 14.656,-21.806 h0.6
M5 Assembly Top:
  lines w0.254: -7.417,-23.626 160.223,-23.626 ; -7.417,-18.462 160.274,-18.462 ; -7.417,-13.297 -7.417,-28.791 94.31,-28.791 160.274,-28.791 160.274,-13.297 -7.404,-13.297 -7.404,-28.791 32.614,-28.791 ; 55.194,-28.791 55.194,-13.297 ; 87.376,-18.462 87.376,-13.297 ; 108.712,-18.462 108.712,-13.297 ; 124.511,-28.956 124.511,-23.804
  text "COMPONENTS MARKED 'DNP' SHOULD NOT BE POPULATED." at 28.799,-8.09 h0.6
  text "ASSEMBLY VARIANT:" at 29.286,-11.024 h0.6
  text ".VariantName" at 55.601,-11.024 h0.6
  text "PCB VIEWED FROM TOP SIDE" at -5.804,-16.654 h0.6
  text "BOARD #:" at 57.099,-16.654 h0.6
  text ".PRJ_Number" at 70.955,-16.654 h0.6
  text "REV:" at 92.405,-16.654 h0.6
  text ".PCB_Rev" at 99.809,-16.654 h0.6
  text "SVN REV:" at 113.69,-16.654 h0.6
  text ".VersionControl_RevNumber" at 126.543,-16.654 h0.6
  text "TID #:" at 57.099,-21.819 h0.6
  text ".TID" at 70.955,-21.819 h0.6
  text "PLOT NAME =" at -5.804,-27.034 h0.6
  text ".plot_File_Name" at 14.656,-27.034 h0.6
  text "GENERATED    :" at 57.15,-27.034 h0.6
  text ".Print_Date" at 79.235,-27.034 h0.6
  text ".Print_Time" at 97.752,-27.034 h0.6
  text "TEXAS INSTRUMENTS" at 129.87,-27.034 h0.6
M6 Assembly Bottom:
  lines w0.254: -7.429,-18.474 160.261,-18.474 ; -7.379,-23.639 160.261,-23.639 ; 28.334,-28.969 28.334,-23.817 ; 44.133,-18.474 44.133,-13.31 ; 65.468,-18.474 65.468,-13.31 ; 97.65,-28.804 97.65,-13.31 ; 120.231,-28.804 160.249,-28.804 160.249,-13.31 -7.429,-13.31 -7.429,-28.804 58.534,-28.804 160.261,-28.804 160.261,-13.31
  text "COMPONENTS MARKED 'DNP' SHOULD NOT BE POPULATED." at 154.991,-8.077 h0.6
  text ".VariantName" at 128.473,-11.024 h0.6
  text "ASSEMBLY VARIANT:" at 154.864,-11.024 h0.6
  text ".VersionControl_RevNumber" at 26.302,-16.667 h0.6
  text "SVN REV:" at 39.154,-16.667 h0.6
  text ".PCB_Rev" at 53.035,-16.667 h0.6
  text "REV:" at 60.439,-16.667 h0.6
  text ".PRJ_Number" at 81.89,-16.667 h0.6
  text "BOARD #:" at 95.745,-16.667 h0.6
  text "PCB VIEWED FROM BOTTOM SIDE" at 158.648,-16.667 h0.6
  text ".TID" at 81.89,-21.831 h0.6
  text "TID #:" at 95.745,-21.831 h0.6
  text "TEXAS INSTRUMENTS" at 22.974,-27.047 h0.6
  text ".Print_Time" at 55.093,-27.047 h0.6
  text ".Print_Date" at 73.609,-27.047 h0.6
  text "GENERATED    :" at 95.694,-27.047 h0.6
  text ".plot_File_Name" at 138.189,-27.047 h0.6
  text "PLOT NAME =" at 158.648,-27.047 h0.6
M9 Title Sheet:
  drawing of 57 lines, arcs and shapes, not listed
  text "1" at 18.792,204.127 h0.6
  text "2" at 82.182,204.127 h0.6
  text "3" at 145.411,204.127 h0.6
  text "4" at 209.08,204.127 h0.6
  text "5" at 272.555,204.127 h0.6
  text "6" at 336.182,204.127 h0.6
  text "A" at -10.579,175.095 h0.6
  text "A" at 365.341,175.095 h0.6
  text "B" at -10.579,114.643 h0.6
  text "B" at 365.341,114.643 h0.6
  text "C" at -10.579,54.318 h0.6
  text "C" at 365.341,54.318 h0.6
  text "PROJECT TITLE:" at 288.125,7.048 h0.6
  text ".PRJ_Title" at 289.395,3.662 h0.6
  text "DESIGNED FOR:" at 288.125,-0.597 h0.6
  text ".PRJ_Customer" at 289.395,-4.153 h0.6
  text "D" at -10.579,-5.88 h0.6
  text "D" at 365.341,-5.88 h0.6
  text "FILE NAME:" at 288.125,-8.217 h0.6
  text ".PCB_File_Name_No_Path" at 289.395,-11.265 h0.6
  text "Texas Instruments (TI) and/or its licensors do not warrant the accuracy or completeness of this specification" at 161.9,-15.376 h0.6
  text "ENGINEER:" at 288.125,-15.583 h0.6
  text "LAYOUT BY:" at 326.352,-15.583 h0.6
  text "or any information contained therein. TI and/or its licensors do not warrant that this design will meet" at 160.757,-18.237 h0.6
  text ".PRJ_Engineer" at 289.395,-19.52 h0.6
  text ".PCB_Layout" at 327.635,-19.52 h0.6
  text "the specifications, will be suitable for your application or fit for any particular purpose, or will operate in" at 160.757,-21.099 h0.6
  text ".Layer_Name" at 14.656,-21.806 h0.6
  text "ALTIUM DESIGNER VERSION:" at 326.352,-23.457 h0.6
  text "an implementation. TI and/or its licensors do not warrant that the design is production worthy. You should" at 160.757,-23.961 h0.6
  text "completely validate and test your design implementation to confirm the system functionality for your application." at 161.9,-26.822 h0.6
  text ".print_Scale" at 289.395,-26.843 h0.6
  text ".Application_BuildNumber" at 327.635,-26.843 h0.6
  text "1" at 18.792,-32.093 h0.6
  text "2" at 82.182,-32.093 h0.6
  text "3" at 145.411,-32.093 h0.6
  text "4" at 209.08,-32.093 h0.6
  text "5" at 272.555,-32.093 h0.6
  text "6" at 336.182,-32.093 h0.6
M10 Fab Notes:
  drawing of 189 lines, arcs and shapes, not listed
  text "DESIGN INFORMATION" at 314.503,161.447 h0.6
  text "MIN. TRACK WIDTH:" at 298.131,158.091 h0.6
  text "8" at 325.976,158.091 h0.6
  text "MIL" at 329.907,158.091 h0.6
  text "7.874" at 321.75,155 h0.6
  text "MIN. CLEARANCE:" at 298.131,154.938 h0.6
  text "MIL" at 329.907,154.938 h0.6
  text "MIN. VIA PAD SIZE:" at 298.131,151.785 h0.6
  text "24" at 325.214,151.785 h0.6
  text "MIL" at 329.907,151.785 h0.6
  text "0.05mm (2MIL)" at 315.784,148.486 h0.6
  text "MINIMUM ANNULAR RING" at 289.769,148.277 h0.6
  text "EXTERNAL" at 333.768,148.277 h0.6
  text "PER" at 294.849,145.48 h0.6
  text "IPC-D-275 CLASS 2 LEVEL C" at 300.437,145.48 h0.6
  text "MIL, HOLES" at 338.238,142.928 h0.6
  text "+/-" at 328.27,142.709 h0.6
  text "+/-" at 349.961,142.709 h0.6
  text "REGISTRATION TOLERANCES:" at 289.769,142.682 h0.6
  text "METAL" at 320.243,142.682 h0.6
  text "5" at 334.879,142.683 h0.6
  text "3" at 356.037,142.683 h0.6
  text "MIL" at 358.99,142.682 h0.6
  text "HOLE SIZE TOLERANCE (UNLESS OTHERWISE SPECIFIED):" at 289.769,140.185 h0.6
  text "+/-" at 349.961,140.112 h0.6
  text "3" at 356.037,140.085 h0.6
  text "MIL" at 358.99,140.085 h0.6
  text "MATERIAL:" at 287.87,136.589 h0.6
  text "FR-4 High Tg" at 312.926,133.324 h0.6
  text "X" at 309.257,133.122 h0.6
  text "FR-4" at 298.563,133.007 h0.6
  text "OTHER" at 336.358,133.007 h0.6
  text "62 MIL (1.6mm) +/-10%" at 306.694,129.374 h0.6
  text "X" at 303.643,129.312 h0.6
  text "THICKNESS:" at 289.769,129.165 h0.6
  text "OTHER" at 339.33,129.165 h0.6
  text "TOLERANCE:" at 289.769,125.652 h0.6
  text "X" at 311.314,125.652 h0.6
  text "ANSI IPC-6012 TYPE 3 CLASS 2" at 315.836,125.652 h0.6
  text "OTHER +/-" at 315.835,121.989 h0.6
  text "BOW & TWIST:" at 289.769,118.302 h0.6
  text "X" at 311.314,118.302 h0.6
  text "ANSI IPC-6012 TYPE 3 CLASS 2" at 315.836,118.302 h0.6
  text "OTHER +/-" at 315.835,114.576 h0.6
  text "DRILLING:" at 287.87,111.258 h0.6
  text "NC_DRILL FILES" at 332.599,108.586 h0.6
  text "REFERENCE:" at 289.769,108.486 h0.6
  text "X" at 306.463,108.484 h0.6
  text "AS SHOWN" at 310.984,108.486 h0.6
  text "X" at 329.348,108.486 h0.6
  text "OTHER" at 340.168,104.873 h0.6
  text "PTH COPPER THICKNESS:" at 289.761,104.783 h0.6
  text "X" at 318.697,104.783 h0.6
  text "20-30 um" at 321.948,104.783 h0.6
  text "BOARD FINISH:" at 287.87,101.034 h0.6
  text "SILKSCREEN:" at 291.812,98.237 h0.6
  text "X" at 316.14,98.237 h0.6
  text "TOP" at 319.112,98.237 h0.6
  text "X" at 329.094,98.237 h0.6
  text "BOTTOM" at 332.091,98.237 h0.6
  text "SILKSCREEN COLOR:" at 291.812,94.295 h0.6
  text "X" at 316.115,94.295 h0.6
  text "WHITE" at 319.112,94.295 h0.6
  text "OTHER" at 332.091,94.295 h0.6
  text "X" at 319.442,90.652 h0.6
  text "GREEN" at 322.439,90.652 h0.6
  text "OTHER" at 338.136,90.652 h0.6
  text "SOLDER RESIST COLOR:" at 291.812,90.477 h0.6
  text "X" at 319.442,86.734 h0.6
  text "MATTE" at 322.439,86.734 h0.6
  text "SEMI-GLOSS" at 338.125,86.717 h0.6
  text "IMMERSION GOLD (ENIG)" at 314.819,82.345 h0.6
  text "ENEPIG" at 348.793,82.162 h0.6
  text "SURFACE FINISH:" at 287.87,82.136 h0.6
  text "X" at 310.298,82.136 h0.6
  text "IMM. TIN/SILVER OR EQUIV" at 296.24,78.649 h0.6
  text "OTHER" at 332.599,78.549 h0.6
  text "ARRAY/PANEL:" at 287.87,74.602 h0.6
  text "CUT AND TRIM PER M1 BOARD OUTLINE" at 314.819,74.393 h0.6
  text "N.C. ROUTE" at 314.819,70.94 h0.6
  text "X" at 332.295,70.94 h0.6
  text "V. SCORE" at 336.816,70.94 h0.6
  text "CERTIFICATION:" at 287.87,67.66 h0.6
  text "MATERIALS AND WORKMANSHIP FOR ALL PCBS" at 306.285,67.66 h0.6
  text "TO MEET OR EXCEED THE REQUIREMENTS OF:" at 306.285,65.271 h0.6
  text "X" at 297.078,62.003 h0.6
  text "ANSI IPC-A-600F CLASS ->" at 300.329,62.003 h0.6
  text "X" at 342.188,62.003 h0.6
  text "2" at 344.982,62.003 h0.6
  text "1" at 336.981,61.965 h0.6
  text "3" at 353.973,61.965 h0.6
  text "X" at 317.702,58.252 h0.6
  text "RoHS" at 320.953,58.252 h0.6
  text "OTHER" at 337.321,58.252 h0.6
  text "PER ORDER" at 347.407,58.252 h0.6
  text "ALL BOARDS MUST MEET OR EXCEED UL94-V0 REQUIREMENTS." at 288.569,54.345 h0.6
  text "PCB MUST BEAR THE UL94V-0 UL REGISTERED MATERIAL ID NUMBER" at 288.569,51.397 h0.6
  text "ADDITIONAL REQUIREMENTS:" at 287.87,47.094 h0.6
  text "MICROSECTION:" at 289.769,44.373 h0.6
  text "YES" at 312.775,44.373 h0.6
  text "REQUIRED" at 334.657,40.707 h0.6
  text "BARE BOARD ELEC. TEST:" at 289.769,40.634 h0.6
  text "NONE" at 322.935,40.634 h0.6
  text "X" at 331.66,40.634 h0.6
  text "PER ORDER" at 349.693,40.634 h0.6
  text "XX MIL VIAS REQUIRE NON-CONDUCTIVE FILL AND PLANARIZE" at 294.04,35.428 h0.6
  text "XX MIL VIAS REQUIRE CONDUCTIVE FILL AND PLANARIZE" at 294.243,32.787 h0.6
  text "OUTER XX MIL TRACES REQUIRE 50 OHM SINGLE-ENDED IMPEDANCE" at 294.218,28.637 h0.6
  text "LAYER 2 & 3 (INNER LAYERS) XX MIL WIDE, XX MIL SPACE / TRACES REQUIRE 100 OHM DIFFERENTIAL IMPEDANCE" at 294.015,22.65 h0.6
  text ".Layer_Name" at 14.656,-21.806 h0.6
M11 Gerber Information:
  lines w0.254: -7.417,-23.626 160.223,-23.626 ; -7.417,-18.462 160.274,-18.462 ; -7.417,-13.297 -7.417,-28.791 94.31,-28.791 160.274,-28.791 160.274,-13.297 -7.404,-13.297 -7.404,-28.791 32.614,-28.791 ; 55.194,-28.791 55.194,-13.297 ; 87.376,-18.462 87.376,-13.297 ; 108.712,-18.462 108.712,-13.297 ; 124.511,-28.956 124.511,-23.804
  text "ALL ARTWORK VIEWED FROM TOP SIDE" at -5.804,-16.654 h0.6
  text "BOARD #:" at 57.099,-16.654 h0.6
  text ".PRJ_Number" at 70.955,-16.654 h0.6
  text "REV:" at 92.405,-16.654 h0.6
  text ".PCB_Rev" at 99.809,-16.654 h0.6
  text "SVN REV:" at 113.69,-16.654 h0.6
  text ".VersionControl_RevNumber" at 126.543,-16.654 h0.6
  text "LAYER NAME =" at -5.804,-21.806 h0.6
  text "TID #:" at 57.099,-21.819 h0.6
  text ".TID" at 70.955,-21.819 h0.6
  text "PLOT NAME =" at -5.804,-27.034 h0.6
  text ".plot_File_Name" at 14.656,-27.034 h0.6
  text "GENERATED    :" at 57.15,-27.034 h0.6
  text ".Print_Date" at 79.235,-27.034 h0.6
  text ".Print_Time" at 97.752,-27.034 h0.6
  text "TEXAS INSTRUMENTS" at 129.87,-27.034 h0.6
M12 Stackup:
  drawing of 295 lines, arcs and shapes, not listed
  text "Layer" at 249.469,200.023 h1.52
  text "Name" at 259.88,200.023 h1.52
  text "Material" at 283.496,200.023 h1.52
  text "Thickness" at 305.334,200.023 h1.52
  text "Constant" at 321.84,200.023 h1.52
  text "Board Layer Stack" at 336.314,200.023 h1.52
  text "Top Overlay" at 259.88,196.975 h1.52
  text "Top Solder" at 259.88,193.927 h1.52
  text "Solder Resist" at 283.496,193.927 h1.52
  text "0.40mil" at 305.334,193.927 h1.52
  text "3.5" at 321.84,193.927 h1.52
  text "1" at 249.469,190.879 h1.52
  text "Top Layer" at 259.88,190.879 h1.52
  text "2.76mil" at 305.334,190.879 h1.52
  text "Dielectric 1" at 259.88,187.831 h1.52
  text "PP-016" at 283.496,187.831 h1.52
  text "4.60mil" at 305.334,187.831 h1.52
  text "4.4" at 321.84,187.831 h1.52
  text "2" at 249.469,184.783 h1.52
  text "Layer 1" at 259.88,184.783 h1.52
  text "CF-004" at 283.496,184.783 h1.52
  text "2.76mil" at 305.334,184.783 h1.52
  text "Dielectric1" at 259.88,181.735 h1.52
  text "Core-037" at 283.496,181.735 h1.52
  text "21.00mil" at 305.334,181.735 h1.52
  text "4.8" at 321.84,181.735 h1.52
  text "3" at 249.469,178.687 h1.52
  text "Layer 2" at 259.88,178.687 h1.52
  text "CF-004" at 283.496,178.687 h1.52
  text "2.76mil" at 305.334,178.687 h1.52
  text "Dielectric 2" at 259.88,175.639 h1.52
  text "PP-016" at 283.496,175.639 h1.52
  text "4.60mil" at 305.334,175.639 h1.52
  text "4.4" at 321.84,175.639 h1.52
  text "4" at 249.469,172.591 h1.52
  text "Bottom Layer" at 259.88,172.591 h1.52
  text "2.76mil" at 305.334,172.591 h1.52
  text "Bottom Solder" at 259.88,169.543 h1.52
  text "Solder Resist" at 283.496,169.543 h1.52
  text "0.40mil" at 305.334,169.543 h1.52
  text "3.5" at 321.84,169.543 h1.52
  text "Bottom Overlay" at 259.88,166.495 h1.52
  text ".Layer_Name" at 14.656,-21.806 h0.6
M13 Component Bodies Top:
  text ".Layer_Name" at 14.656,-21.806 h0.6
M14 Component Bodies Bottom:
  text ".Layer_Name" at 14.656,-21.806 h0.6
M15 Courtyards Top:
  text ".Layer_Name" at 14.656,-21.806 h0.6
M16 Courtyards Bottom:
  text ".Layer_Name" at 14.656,-21.806 h0.6
Drill Drawing:
  circle w0.254: c136.238,77.258 r0.702
  lines w0.254: 135.537,70.241 136.94,70.241 136.94,71.644 135.537,71.644 135.537,70.241 ; 135.537,73.749 135.888,73.749 135.888,73.398 136.589,73.398 136.589,73.749 136.94,73.749 136.94,74.451 136.589,74.451 136.589,74.802 135.888,74.802 135.888,74.451 135.537,74.451 135.537,73.749 ; 135.537,79.714 136.238,80.065 136.94,79.714 136.589,80.415 136.94,81.117 136.238,80.766 135.537,81.117 135.888,80.415 135.537,79.714 ; 135.537,83.222 135.888,83.222 136.238,82.871 136.589,83.222 136.94,83.222 136.589,83.573 136.94,83.924 136.589,83.924 136.238,84.275 135.888,83.924 135.537,83.924 135.888,83.573 135.537,83.222
  lines w0.305: 134.264,69.293 216.344,69.293 ; 134.264,85.082 216.344,85.082 ; 142.846,66.136 142.846,88.24 ; 151.279,66.136 151.279,88.24 ; 167.448,66.136 167.448,88.24 ; 174.03,66.136 174.03,88.24 ; 183.559,66.136 183.559,88.24 ; 201.957,66.136 201.957,88.24 ; 134.264,66.136 216.344,66.136 216.344,88.24 134.264,88.24 134.264,66.136
  text "Symbol" at 136.159,86.029 h1.83
  text "Quantity" at 143.793,86.029 h1.83
  text "Finished Hole Size" at 152.226,86.029 h1.83
  text "Plated" at 168.395,86.029 h1.83
  text "Hole Type" at 174.977,86.029 h1.83
  text "Drill Layer Pair" at 184.506,86.029 h1.83
  text "Hole Tolerance" at 202.904,86.029 h1.83
  text "14" at 143.793,82.871 h1.52
  text "7.87mil (0.200mm)" at 152.226,82.871 h1.52
  text "PTH" at 168.395,82.871 h1.52
  text "Round" at 174.977,82.871 h1.52
  text "Top Layer - Bottom Layer" at 184.506,82.871 h1.52
  text "203" at 143.793,79.714 h1.52
  text "9.84mil (0.250mm)" at 152.226,79.714 h1.52
  text "PTH" at 168.395,79.714 h1.52
  text "Round" at 174.977,79.714 h1.52
  text "Top Layer - Bottom Layer" at 184.506,79.714 h1.52
  text "8" at 143.793,76.556 h1.52
  text "13.78mil (0.350mm)" at 152.226,76.556 h1.52
  text "PTH" at 168.395,76.556 h1.52
  text "Round" at 174.977,76.556 h1.52
  text "Top Layer - Bottom Layer" at 184.506,76.556 h1.52
  text "4" at 143.793,73.398 h1.52
  text "23.62mil (0.600mm)" at 152.226,73.398 h1.52
  text "PTH" at 168.395,73.398 h1.52
  text "Round" at 174.977,73.398 h1.52
  text "Top Layer - Bottom Layer" at 184.506,73.398 h1.52
  text "6" at 143.793,70.241 h1.52
  text "64.96mil (1.650mm)" at 152.226,70.241 h1.52
  text "PTH" at 168.395,70.241 h1.52
  text "Round" at 174.977,70.241 h1.52
  text "Top Layer - Bottom Layer" at 184.506,70.241 h1.52
  text "235 Total" at 143.793,67.083 h1.52
  text ".Layer_Name" at 14.656,-21.806 h0.6
M17 Embedded Cavity:
  text ".Layer_Name" at 14.656,-21.806 h0.6
M18 Embedded Assembly:
  text ".Layer_Name" at 14.656,-21.806 h0.6
M19 Embedded Keepout:
  text ".Layer_Name" at 14.656,-21.806 h0.6

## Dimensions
0,-10.16 to 25.4,-10.16 on M2 Board Dimensions
0,0 to 77.75,0 on M2 Board Dimensions
0,0 to 32.25,37.75 on M2 Board Dimensions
